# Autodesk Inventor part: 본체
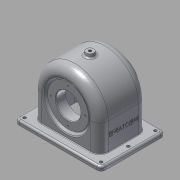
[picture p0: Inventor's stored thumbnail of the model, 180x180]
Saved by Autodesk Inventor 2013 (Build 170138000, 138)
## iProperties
Created: 2015-09
Part Number: 본체
Material: 알루미늄 6061
Document SubType Name: Modeling
Designer: dgall
Density: 2.71 g/cm^3
Mass: 672.576 g
Surface Area: 885.4 cm^2
Volume: 248.183 cm^3
Author: dgall
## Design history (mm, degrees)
sketch "스케치1"
  geometry: L1 (-70, 52)-(70, 52); L2 (70, 52)-(70, -52); L3 (70, -52)-(-70, -52); L4 (-70, -52)-(-70, 52); 1 further point
  constraints: 8 end point, 2 parallel, 1 horizontal, 1 perpendicular
  dimensions: "d1" = 140 distance of L2.end L3.end; "d3" = 104 distance of L1.end L2.end; "d4" = 52 distance from line of L1 point (0, 0); "d5" = 70 distance from line of L2 point (0, 0)
node "작업 평면1"
sketch "스케치2"
  geometry: L1 (0, 0)-(140, 0) reference; L2 (140, 7)-(0, 7) reference; L3 (16, 50.609)-(16, 7); L4 (124, 50.609)-(124, 7); A1 r 54 centre (70, 50.609) between (124, 50.609) and (16, 50.609); 1 further point
  constraints: 4 end point, 2 perpendicular, 2 point on circle, 2 point on line, 2 tangent, 1 centre point
  dimensions: "d14" = 0 horizontal distance of point (70, 0) A1.centre
extrude "돌출2" join sketch "스케치2" stored distance "d15" = 77; taper "d16" = 0 deg
feature "쉘1" dims "d17" = 5
fillet "모깎기1" dims "d20" = 14
sketch "스케치3"
  geometry: C1 r 31 at (70, -50.609); A1 r 40 centre (70, -50.609) between (30, -50.609) and (110, -50.609) reference; 1 further point
  constraints: 1 centre point, 1 coincident
  dimensions: "d21" = 62 diameter of C1
extrude "돌출4" join sketch "스케치3" distance "d23" = 10; taper "d24" = 0 deg
sketch "스케치4"
  geometry: C1 r 31 at (0, 0) reference; C2 r 20 at (0, 0); 1 further point
  constraints: 1 centre point, 1 coincident
  dimensions: "d25" = 40 diameter of C2
extrude "돌출5" cut sketch "스케치4" distance "d27" = 20; taper "d28" = 0 deg
node "작업 평면2"
sketch "스케치5"
  geometry: L1 (0, -14)-(-40, -14) reference; L2 (43.609, -14)-(0, -14) reference; L3 (0, -9)-(43.609, -9) reference; L4 (-49, -9)-(0, -9) reference; L5 (0, -14)-(0, 5); L6 (0, 5)-(-28, 5); L7 (-28, 5)-(-39.747, -9); L8 (-39.747, -9)-(0, -9); L9 (0, -9)-(0, 5); 1 further point
  constraints: 10 end point, 2 perpendicular, 1 collinear, 1 point on line
  dimensions: "d29" = 0 distance from line of L3.start L5; "d30" = 19 distance of L5.start L5.end; "d31" = 0 distance from line of L1 L5.start; "d32" = 50 deg angle of L6 L7; "d33" = 56 diameter of L6.end L5
revolve "회전1" sketch "스케치5" stored, may be unused: angle "d34" = 90 deg
sketch "스케치6"
  geometry: C1 r 28 at (0, 0) reference; C2 r 20 at (0, 0); 1 further point
  constraints: 1 centre point, 1 coincident
  dimensions: "d35" = 40 diameter of C2
extrude "돌출6" cut sketch "스케치6" distance "d37" = 16; taper "d38" = 0 deg
node "작업 평면3"
sketch "스케치7"
  geometry: L1 (-39.747, -9)-(-28, 5) reference; L2 (0, 0)-(0, -14) reference; L3 (0, -14)-(0, -14) reference; L4 (0, 0)-(0, -14) reference; L5 (0, 0)-(0, 0) reference; L6 (0, -14)-(-40, -14) reference; L7 (-33, -14)-(-33, -11); L8 (-33, -11)-(0, -11); 1 further point
  constraints: 4 end point, 2 perpendicular, 2 point on line
  dimensions: "d42" = 3 distance of L7.start L7.end; "d44" = 66 diameter of L7 L2
  node "투영된 루프1"
sketch "스케치8"
  geometry: C1 r 33 at (70, 50.609); A1 r 40 centre (70, 50.609) between (110, 50.609) and (30, 50.609) reference; 1 further point
  constraints: 1 centre point, 1 coincident
  dimensions: "d45" = 66 diameter of C1
extrude "돌출7" cut sketch "스케치8" distance "d47" = 3; taper "d48" = 0 deg
fillet "모깎기2" dims "d49" = 9
extrude "돌출8" join sketch "스케치1" distance "d50" = 7; taper "d51" = 0 deg
node "작업 평면4"
sketch "스케치9"
  geometry: L1 (0, -14)-(-40, -14) reference; L2 (-39.747, -9)-(-28, 5) reference; L3 (33, -14)-(-33, -14) reference; L4 (-20, -11)-(20, -11) reference; L5 (0, -14)-(0, 7.909); L6 (-37.416, -14)-(0, -14); L7 (-37.416, -14)-(-33, -8.737); L8 (33, -11)-(-33, -11) reference; L9 (-33, -11)-(-33, -8.737); L10 (-33, -11)-(0, -11); L11 (0, -14)-(0, -11); 1 further point
  constraints: 12 end point, 2 collinear, 1 midpoint, 1 parallel, 1 perpendicular, 1 point on line
  dimensions: "d53" = 5 distance between parallel lines of L2 L7
revolve "회전2" sketch "스케치9" stored, may be unused: angle "d54" = 90 deg
node "작업 평면5"
sketch "스케치10"
  geometry: L1 (-24.61, 34.544)-(24.61, 34.544); L2 (24.61, 34.544)-(24.61, 25.456); L3 (24.61, 25.456)-(-24.61, 25.456); L4 (-24.61, 25.456)-(-24.61, 34.544); L5 (-24.61, 30)-(24.61, 30); L6 (0, 34.544)-(0, 25.456); L7 (52, 0)-(-52, 0) reference; L8 (-38.5, 50.609)-(-38.5, 7) reference; 1 further point
  constraints: 4 end point, 4 midpoint, 2 other
  dimensions: "d56" = 30 distance between parallel lines of L7 L5; "d57" = 38.5 distance between parallel lines of L6 L8
feature "엠보싱1" sketch "스케치10" dims "d58" = 0.5, "d59" = 0
fillet "모깎기3" dims "d60" = 0.5
chamfer "모따기1" distance "d61" = 1; stored, may be unused: second distance "d62" = 2, angle "d63" = 45 deg
chamfer "모따기2" distance "d64" = 1; stored, may be unused: second distance "d65" = 2, angle "d66" = 45 deg
sketch "스케치11" dims "d67" = 56
  geometry: L1 (0, 0)-(0, 28); C1 r 21 at (0, 0) reference; 1 further point
  constraints: 2 end point, 1 coincident, 1 vertical, 1 vertical alignment, 2 other
hole "구멍1" sketch "스케치11" at (0, 28) diameter "d69" = 2.459; stored, may be unused: countersink angle "d73" = 90 deg, drill point angle "d75" = 118 deg; dims "d70" = 7, "d71" = 4, "d72" = 2, "d74" = 9
sketch "스케치12" dims "d79" = 48
  geometry: L1 (0, 0)-(0, -24); C1 r 21 at (0, 0) reference; 1 further point
  constraints: 2 end point, 1 coincident, 1 vertical, 1 vertical alignment, 2 other
hole "구멍2" sketch "스케치12" at (0, -24) diameter "d81" = 2.459; stored, may be unused: countersink angle "d85" = 90 deg, drill point angle "d87" = 118 deg; dims "d82" = 6, "d83" = 4, "d84" = 2, "d86" = 8
node "작업 평면6"
sketch "스케치13"
  geometry: C1 r 6 at (0, 0); 1 further point
  constraints: 1 centre point, 1 coincident
  dimensions: "d92" = 12 diameter of C1
extrude "돌출9" join sketch "스케치13" distance "d94" = 7; taper "d95" = 10 deg
fillet "모깎기4" dims "d96" = 3
fillet "모깎기5" dims "d97" = 7
fillet "모깎기6" dims "d98" = 3
fillet "모깎기7" dims "d99" = 1
sketch "스케치14"
  geometry: C1 r 6 at (0, 0) reference
hole "구멍3" sketch "스케치14" at (0, 0) diameter "d100" = 4.459; stored, may be unused: countersink angle "d104" = 90 deg, drill point angle "d106" = 118 deg; dims "d101" = 6, "d102" = 4, "d103" = 2, "d105" = 8
sketch "스케치15"
  geometry: L1 (-40, -33.5)-(40, -33.5) reference; L2 (49, -24.5)-(49, 24.5) reference; L3 (40, 33.5)-(-40, 33.5) reference; L4 (-49, 24.5)-(-49, -24.5) reference; A1 r 9 centre (-40, -24.5) between (-49, -24.5) and (-40, -33.5) reference; A2 r 9 centre (40, -24.5) between (40, -33.5) and (49, -24.5) reference; A3 r 9 centre (40, 24.5) between (49, 24.5) and (40, 33.5) reference; A4 r 9 centre (-40, 24.5) between (-40, 33.5) and (-49, 24.5) reference; 1 further point
extrude "돌출10" cut sketch "스케치15" stored distance "d107" = 10; taper "d108" = 0 deg
sketch "스케치16"
  geometry: L1 (63, 52)-(-63, 52) reference; L2 (-63, -52)-(63, -52) reference; L3 (-70, 45)-(-70, -45) reference; L4 (70, -45)-(70, 45) reference; C1 r 2.5 at (-62, 44); C2 r 2.5 at (-62, -44); C3 r 2.5 at (62, -44); C4 r 2.5 at (62, 44); C5 r 2.5 at (62, 0); C6 r 2.5 at (-62, 0); 1 further point
  constraints: 6 centre point
  dimensions: "d122" = 8 distance from line of L1 C4.centre; "d123" = 8 distance from line of L2 C3.centre; "d124" = 8 distance from line of L2 C2.centre; "d128" = 5 diameter of C1; "d129" = 5 diameter of C2; "d130" = 5 diameter of C3; "d131" = 5 diameter of C4; "d132" = 5 diameter of C5; "d133" = 5 diameter of C6; "d142" = 8 distance from line of L3 C2.centre; "d143" = 8 distance from line of C6.centre L3; "d144" = 8 distance from line of L3 C1.centre; "d145" = 8 distance from line of L4 C4.centre; "d146" = 8 distance from line of L4 C5.centre; "d147" = 8 distance from line of L4 C3.centre; "d148" = 44 distance of C3.centre C5.centre; "d149" = 44 distance of C2.centre C6.centre; "d150" = 44 distance of C6.centre C1.centre
extrude "돌출11" cut sketch "스케치16" stored distance "d134" = 10; taper "d135" = 0 deg
sketch "스케치17"
  geometry: C1 r 2.5 at (-62, 44) reference; C2 r 2.5 at (-30.624, 0); C3 r 2.5 at (-62, 0); 1 further point
  constraints: 2 centre point
  dimensions: "d138" = 44 distance of C1.centre C3.centre; "d139" = 5 diameter of C3
extrude "돌출12" cut sketch "스케치17" stored distance "d140" = 10; taper "d141" = 0 deg
fillet "모깎기8" dims "d151" = 3
node "솔리드1"
pattern_circular "원형 패턴1" dims angle "d77" = 360 deg
pattern_circular "원형 패턴2" dims angle "d89" = 360 deg
other parameters: "d13" = 108, "d55" = 81.25
